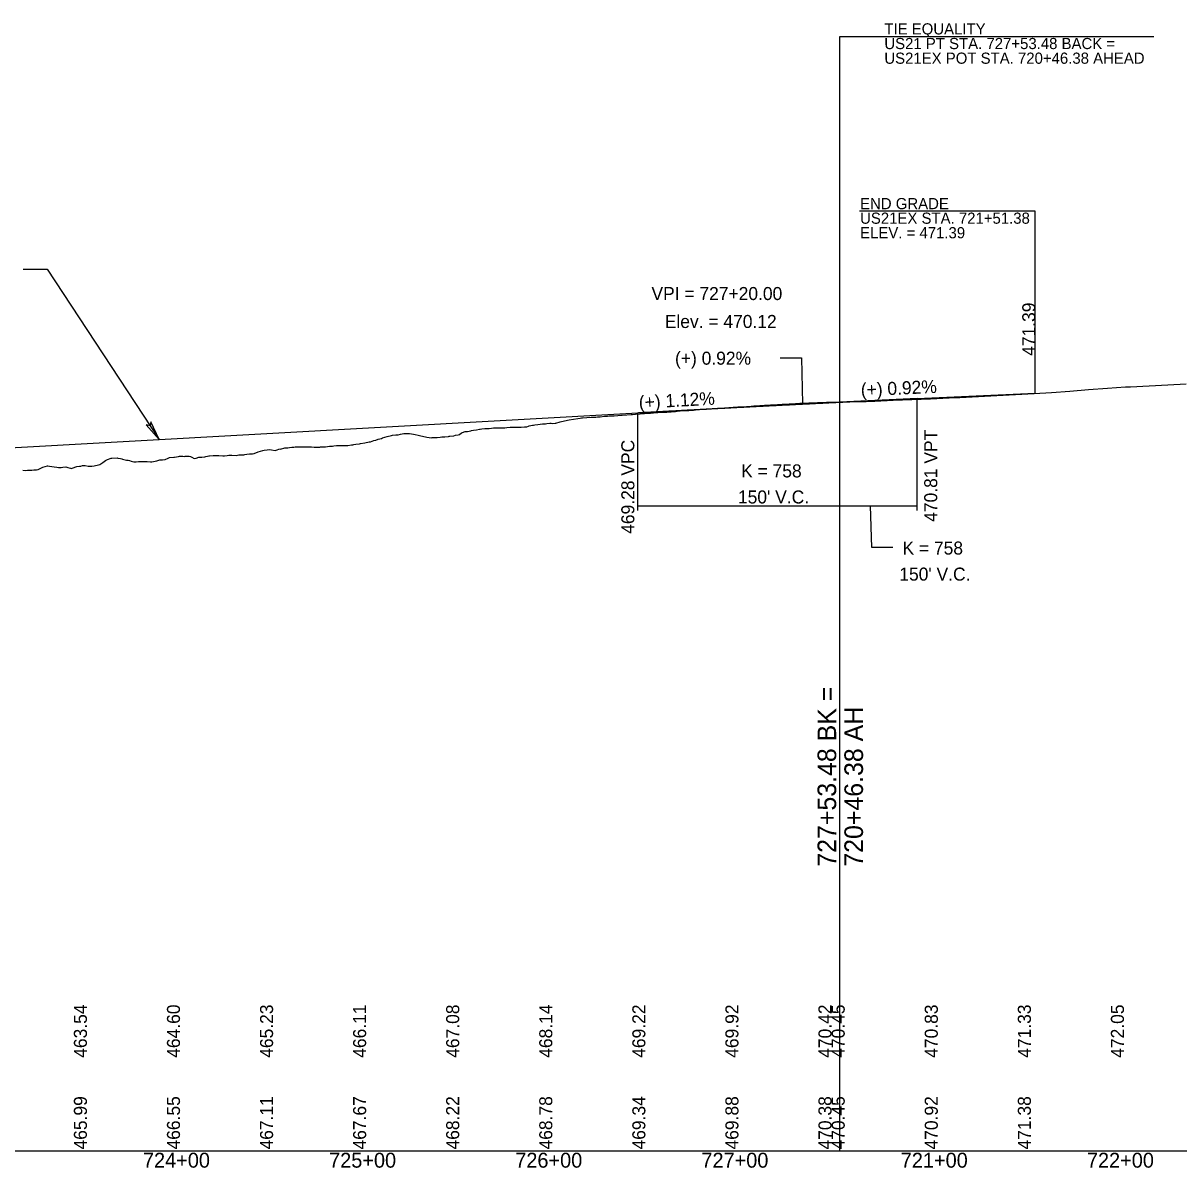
# Model space of a CAD drawing. Extents: x 2017200 to 2047700, y 854850 to 893350.
# Drawn here: x 2025315 to 2025936, y 889091 to 889706 of the extents above; entities that cross this region are included whole.
import ezdxf

# ---------------------------------------------------------------- set-up
doc = ezdxf.new("R2010")
doc.units = 0
for name, color, linetype in [('RD_DDB_GradeTX', 7, 'Continuous'), ('RD_DDB_Profile_EX', 7, 'Continuous'), ('RD_DDB_Profile_Lbl', 7, 'Continuous'), ('RD_DDB_Profile_PR', 7, 'Continuous'), ('RD_DDB_StaTX', 7, 'Continuous'), ('RD_DDB_StripGrade', 7, 'Continuous'), ('RD_DDB_VCLbl', 7, 'Continuous'), ('RD_GPK_Profile_Cell', 7, 'Continuous'), ('RD_PD_NON-PLOTTING', 7, 'Continuous')]:
    doc.layers.add(name, color=color, linetype=linetype)

msp = doc.modelspace()

# ---------------------------------------------------------------- linework, layer by layer
at = {"layer": 'RD_DDB_GradeTX'}
for p, q in [((2025645, 889496.42), (2025720, 889500.6)), ((2025753.48, 889502.14), (2025720, 889500.6)), ((2025795, 889504.04), (2025753.48, 889502.14))]:
    msp.add_line(p, q, dxfattribs=at)
for points in [[(2025721.48, 889525.92), (2025732.8, 889525.92), (2025733.46, 889501.22)], [(2025781.92, 889423.96), (2025770.6, 889423.96), (2025770, 889446.42)]]:
    msp.add_lwpolyline(points, dxfattribs=at)
at = {"layer": 'RD_DDB_Profile_EX'}
msp.add_lwpolyline([(2025314.65, 889465.57), (2025315.77, 889465.47), (2025317.04, 889465.48), (2025318.76, 889465.49), (2025319.42, 889465.57), (2025320.44, 889465.71), (2025321.87, 889465.81), (2025322.88, 889465.95), (2025324.19, 889466.64), (2025324.98, 889467.05), (2025325.33, 889467.21), (2025326.64, 889467.62), (2025327.78, 889467.86), (2025328.09, 889467.91), (2025328.96, 889467.75), (2025330.24, 889467.51), (2025331.35, 889467.31), (2025332.8, 889467.14), (2025333.73, 889467.01), (2025334.29, 889466.94), (2025335.17, 889466.92), (2025336.12, 889467.09), (2025337.64, 889467.34), (2025338.67, 889466.97), (2025340.12, 889466.58), (2025340.47, 889466.5), (2025341.06, 889466.72), (2025343.56, 889467.6), (2025345.09, 889467.68), (2025345.66, 889467.8), (2025346.65, 889468), (2025347.58, 889468.07), (2025348.04, 889468), (2025349.73, 889467.72), (2025350.08, 889467.72), (2025350.43, 889467.73), (2025351.59, 889467.78), (2025352.81, 889467.86), (2025355.2, 889468.39), (2025355.88, 889468.54), (2025357.6, 889469.73), (2025358.95, 889470.73), (2025360.12, 889471.34), (2025362.02, 889472.06), (2025362.35, 889472.07), (2025365.18, 889472.12), (2025365.62, 889472.07), (2025367.12, 889471.82), (2025367.72, 889471.71), (2025368.16, 889471.56), (2025369.51, 889471.18), (2025370.27, 889470.97), (2025371.22, 889470.85), (2025371.89, 889470.68), (2025372.82, 889470.44), (2025374.28, 889469.96), (2025375.37, 889469.97), (2025376.66, 889470.18), (2025377.33, 889470.3), (2025379.05, 889470.28), (2025380.5, 889470.24), (2025381.13, 889470.19), (2025381.43, 889470.16), (2025383.08, 889470.03), (2025383.44, 889470.07), (2025383.82, 889470.12), (2025385.66, 889470.39), (2025386.49, 889470.65), (2025388.25, 889471.13), (2025388.59, 889471.13), (2025389.53, 889471.12), (2025390.97, 889471.36), (2025392.58, 889471.93), (2025393.44, 889472.41), (2025395.74, 889472.54), (2025396.05, 889472.56), (2025398.12, 889472.95), (2025398.72, 889473.05), (2025400.51, 889473), (2025401.29, 889472.98), (2025401.7, 889473.1), (2025402.89, 889473.1), (2025403.92, 889473.09), (2025404.73, 889472.95), (2025405.28, 889472.61), (2025406.56, 889471.8), (2025407.77, 889472.09), (2025409.2, 889472.54), (2025410.05, 889472.55), (2025410.8, 889472.57), (2025412.43, 889472.78), (2025412.93, 889472.84), (2025413.83, 889473.16), (2025414.51, 889473.24), (2025414.82, 889473.28), (2025416.86, 889473.49), (2025417.2, 889473.52), (2025419.88, 889473.45), (2025421.97, 889473.35), (2025422.53, 889473.32), (2025422.91, 889473.34), (2025424.36, 889473.52), (2025425.22, 889473.63), (2025425.93, 889473.67), (2025426.84, 889473.6), (2025429.13, 889473.5), (2025430.62, 889473.87), (2025431.51, 889473.87), (2025431.98, 889473.88), (2025433.34, 889473.8), (2025433.9, 889473.9), (2025434.99, 889474.09), (2025436.28, 889474.28), (2025438.01, 889474.37), (2025438.79, 889474.52), (2025441.05, 889475.35), (2025443.44, 889476.07), (2025444.27, 889476.29), (2025445.82, 889476.49), (2025447.09, 889476.66), (2025448.21, 889476.47), (2025450.07, 889476.16), (2025450.59, 889476.32), (2025452.57, 889476.94), (2025453.08, 889476.92), (2025455.36, 889477.53), (2025456.09, 889477.55), (2025456.95, 889477.62), (2025457.75, 889477.72), (2025459.1, 889477.9), (2025460.13, 889477.98), (2025460.95, 889478.05), (2025462.11, 889478.1), (2025462.52, 889478.1), (2025463.76, 889478.11), (2025465.12, 889478.15), (2025466.58, 889478.12), (2025467.29, 889478.1), (2025468.12, 889478.06), (2025469.67, 889478.01), (2025471.13, 889477.98), (2025472.06, 889477.99), (2025473.05, 889478), (2025474.13, 889478), (2025474.44, 889478.01), (2025475.11, 889478.03), (2025476.83, 889478.14), (2025477.14, 889478.16), (2025479.38, 889478.42), (2025480.14, 889478.46), (2025480.84, 889478.5), (2025481.6, 889478.58), (2025483.14, 889478.74), (2025483.98, 889478.77), (2025485.64, 889478.83), (2025486.62, 889478.83), (2025488.75, 889478.88), (2025489.15, 889478.89), (2025491.14, 889479.13), (2025491.85, 889479.21), (2025492.44, 889479.31), (2025493.52, 889479.46), (2025495.37, 889479.72), (2025495.91, 889479.8), (2025498.31, 889480.18), (2025500.68, 889480.73), (2025501.26, 889480.87), (2025503.06, 889481.41), (2025504.22, 889481.76), (2025505.45, 889482.13), (2025507.2, 889482.65), (2025507.83, 889482.85), (2025510.22, 889483.61), (2025512.6, 889484.2), (2025513.18, 889484.35), (2025514.99, 889484.5), (2025516.16, 889484.59), (2025517.37, 889484.85), (2025519.22, 889485.23), (2025519.76, 889485.23), (2025522.26, 889485.21), (2025524.53, 889484.82), (2025525.31, 889484.67), (2025526.91, 889484.34), (2025528.38, 889484.04), (2025529.3, 889483.84), (2025531.68, 889483.37), (2025534.17, 889483.02), (2025534.55, 889483.03), (2025536.45, 889483.11), (2025537.17, 889483.14), (2025538.84, 889483.32), (2025539.6, 889483.4), (2025540.17, 889483.44), (2025540.79, 889483.51), (2025541.22, 889483.55), (2025543.17, 889483.72), (2025543.61, 889483.77), (2025543.92, 889483.81), (2025546.18, 889484.09), (2025547.08, 889484.3), (2025548.38, 889484.61), (2025549.18, 889484.8), (2025550.25, 889485.56), (2025550.76, 889485.75), (2025552.19, 889486.26), (2025553.43, 889486.37), (2025555.19, 889486.72), (2025555.53, 889486.8), (2025556.63, 889487.04), (2025558.2, 889487.25), (2025559.85, 889487.51), (2025560.3, 889487.62), (2025561.21, 889487.83), (2025562.69, 889487.86), (2025563.08, 889487.86), (2025564.21, 889487.99), (2025565.07, 889488.02), (2025566.33, 889488.08), (2025567.46, 889488.23), (2025567.98, 889488.29), (2025569.84, 889488.34), (2025570.23, 889488.35), (2025572.22, 889488.34), (2025572.89, 889488.34), (2025573.54, 889488.37), (2025574.61, 889488.45), (2025576.31, 889488.57), (2025576.99, 889488.57), (2025579.52, 889488.57), (2025581.76, 889488.64), (2025582.29, 889488.65), (2025584.15, 889488.86), (2025584.56, 889488.9), (2025585.3, 889488.89), (2025586.22, 889489.25), (2025586.53, 889489.32), (2025588.32, 889489.68), (2025588.92, 889489.75), (2025589.6, 889489.83), (2025591.3, 889490.11), (2025593.8, 889490.52), (2025595.43, 889490.42), (2025596.07, 889490.55), (2025597.66, 889490.87), (2025598.46, 889490.73), (2025599.18, 889490.6), (2025600.48, 889490.77), (2025600.84, 889490.86), (2025603.23, 889491.45), (2025605.61, 889492.03), (2025608.1, 889492.63), (2025610.38, 889492.99), (2025612.77, 889493.36), (2025614.02, 889493.56), (2025614.69, 889493.62), (2025615.15, 889493.65), (2025617.54, 889493.8), (2025619.92, 889493.95), (2025622.31, 889494.1), (2025623.29, 889494.16), (2025624.69, 889494.28), (2025627.08, 889494.49), (2025628.72, 889494.63), (2025629.46, 889494.68), (2025631.85, 889494.81), (2025632.24, 889494.83), (2025634.23, 889495.01), (2025635.61, 889495.14), (2025636.62, 889495.19), (2025639, 889495.33), (2025641.39, 889495.47), (2025642.04, 889495.51), (2025643.77, 889495.67), (2025646.16, 889495.88), (2025646.53, 889495.92), (2025648.54, 889496.03), (2025650.93, 889496.17), (2025651.84, 889496.22), (2025653.31, 889496.34), (2025655.7, 889496.51), (2025658.08, 889496.65), (2025659.96, 889496.75), (2025660.47, 889496.79), (2025662.85, 889496.97), (2025665.24, 889497.14), (2025666.04, 889497.2), (2025667.65, 889497.35), (2025670.01, 889497.52), (2025672.39, 889497.69), (2025674.78, 889497.85), (2025677.16, 889498.07), (2025677.68, 889498.12), (2025679.55, 889498.24), (2025681.93, 889498.39), (2025684.32, 889498.55), (2025685.44, 889498.62), (2025686.7, 889498.73), (2025687.69, 889498.81), (2025689.09, 889498.9), (2025691.47, 889499.04), (2025693.86, 889499.19), (2025696.24, 889499.33), (2025697.7, 889499.45), (2025698.63, 889499.51), (2025701.01, 889499.66), (2025703.4, 889499.81), (2025705.78, 889499.96), (2025706.08, 889499.98), (2025707.21, 889500.05), (2025708.17, 889500.1), (2025710.55, 889500.25), (2025712.94, 889500.39), (2025715.32, 889500.54), (2025716.22, 889500.59), (2025716.98, 889500.64), (2025717.71, 889500.68), (2025720.09, 889500.82), (2025722.48, 889500.96), (2025724.86, 889501.09), (2025726.32, 889501.18), (2025726.81, 889501.2), (2025727.25, 889501.23), (2025729.63, 889501.36), (2025732.02, 889501.49), (2025734.4, 889501.62), (2025736.79, 889501.75), (2025737.63, 889501.77), (2025739.17, 889501.81), (2025741.56, 889501.88), (2025743.94, 889501.94), (2025746.32, 889502), (2025747.63, 889502.03), (2025748.71, 889502.06), (2025751.09, 889502.12), (2025753.48, 889502.17), (2025757.63, 889502.27), (2025767.63, 889502.51), (2025772.19, 889502.7), (2025782.2, 889503.11), (2025792.22, 889503.53), (2025802.23, 889503.95), (2025812.16, 889504.36), (2025817.9, 889504.65), (2025827.9, 889505.15), (2025837.9, 889505.66), (2025847.9, 889506.17), (2025857.9, 889506.68), (2025867.22, 889507.36), (2025877.04, 889508.07), (2025887.04, 889508.8), (2025897.22, 889509.53), (2025907.01, 889510.24), (2025909.61, 889510.36), (2025919.62, 889510.86), (2025929.62, 889511.35), (2025939.56, 889511.85)], dxfattribs=at)
at = {"layer": 'RD_DDB_Profile_Lbl'}
for points in [[(2025753.48, 889502.08), (2025753.48, 889698.54), (2025922.23, 889698.54)], [(2025858.48, 889506.95), (2025858.48, 889604.61), (2025764.12, 889604.61)], [(2025314.77, 889573.48), (2025327.63, 889573.48), (2025387.8, 889482.08)]]:
    msp.add_lwpolyline(points, dxfattribs=at)
msp.add_lwpolyline([(2025387.8, 889482.08), (2025383.34, 889491.58), (2025382.97, 889489.42), (2025380.84, 889489.93)], close=True, dxfattribs=at)
at = {"layer": 'RD_DDB_Profile_PR'}
for p, q in [((2025795, 889504.04), (2025858.48, 889506.95)), ((2024325, 889422.83), (2025645, 889496.42))]:
    msp.add_line(p, q, dxfattribs=at)
for points in [[(2025645, 889496.42), (2025647.17, 889496.54), (2025649.34, 889496.66), (2025651.51, 889496.78), (2025653.68, 889496.9), (2025655.85, 889497.02), (2025658.02, 889497.14), (2025660.19, 889497.26), (2025662.36, 889497.38), (2025664.53, 889497.49), (2025666.7, 889497.61), (2025668.87, 889497.73), (2025671.04, 889497.85), (2025673.2, 889497.96), (2025675.37, 889498.08), (2025677.54, 889498.2), (2025679.71, 889498.31), (2025681.88, 889498.43), (2025684.05, 889498.55), (2025686.22, 889498.66), (2025688.39, 889498.78), (2025690.56, 889498.89), (2025692.73, 889499), (2025694.9, 889499.12), (2025697.07, 889499.23), (2025699.24, 889499.35), (2025701.41, 889499.46), (2025703.58, 889499.57), (2025705.75, 889499.68), (2025707.92, 889499.8), (2025710.09, 889499.91), (2025712.26, 889500.02), (2025714.43, 889500.13), (2025716.6, 889500.24), (2025718.77, 889500.35), (2025720.94, 889500.46), (2025723.11, 889500.57), (2025725.27, 889500.68), (2025727.44, 889500.79), (2025729.61, 889500.9), (2025731.78, 889501.01), (2025733.95, 889501.12), (2025736.12, 889501.22), (2025738.29, 889501.33), (2025740.46, 889501.44), (2025742.63, 889501.55), (2025744.8, 889501.65), (2025746.97, 889501.76), (2025749.14, 889501.87), (2025751.31, 889501.97), (2025753.48, 889502.08)], [(2025753.48, 889502.08), (2025754.31, 889502.12), (2025755.14, 889502.16), (2025755.97, 889502.2), (2025756.8, 889502.24), (2025757.63, 889502.28), (2025758.46, 889502.32), (2025759.29, 889502.36), (2025760.12, 889502.4), (2025760.95, 889502.44), (2025761.78, 889502.48), (2025762.61, 889502.52), (2025763.44, 889502.56), (2025764.27, 889502.6), (2025765.11, 889502.64), (2025765.94, 889502.68), (2025766.77, 889502.72), (2025767.6, 889502.76), (2025768.43, 889502.8), (2025769.26, 889502.84), (2025770.09, 889502.88), (2025770.92, 889502.92), (2025771.75, 889502.96), (2025772.58, 889502.99), (2025773.41, 889503.03), (2025774.24, 889503.07), (2025775.07, 889503.11), (2025775.9, 889503.15), (2025776.73, 889503.19), (2025777.56, 889503.23), (2025778.39, 889503.27), (2025779.22, 889503.31), (2025780.05, 889503.35), (2025780.88, 889503.39), (2025781.71, 889503.42), (2025782.54, 889503.46), (2025783.37, 889503.5), (2025784.2, 889503.54), (2025785.04, 889503.58), (2025785.87, 889503.62), (2025786.7, 889503.66), (2025787.53, 889503.69), (2025788.36, 889503.73), (2025789.19, 889503.77), (2025790.02, 889503.81), (2025790.85, 889503.85), (2025791.68, 889503.89), (2025792.51, 889503.92), (2025793.34, 889503.96), (2025794.17, 889504), (2025795, 889504.04)]]:
    msp.add_spline(points, degree=3, dxfattribs=at)
at = {"layer": 'RD_DDB_VCLbl'}
for p, q in [((2025795, 889443.92), (2025795, 889504.04)), ((2025645, 889443.92), (2025645, 889496.42)), ((2025645, 889446.42), (2025753.48, 889446.42)), ((2025753.48, 889446.42), (2025795, 889446.42))]:
    msp.add_line(p, q, dxfattribs=at)
at = {"layer": 'RD_GPK_Profile_Cell'}
msp.add_line((2020500, 889100), (2027000, 889100), dxfattribs=at)
at = {"layer": 'RD_PD_NON-PLOTTING'}
msp.add_line((2025753.48, 889100), (2025753.48, 889512.23), dxfattribs=at)

# ---------------------------------------------------------------- texts
at = {"layer": 'RD_DDB_GradeTX'}
msp.add_text('(+) 0.92%', height=7, dxfattribs=at).set_placement((2025664.94, 889522.2))
for s, rotation, p in [('(+) 0.92%', 2.62549, (2025764.9, 889505.2)), ('(+) 1.12%', 3.19108, (2025645.68, 889498.46))]:
    msp.add_text(s, height=7, rotation=rotation, dxfattribs=at).set_placement(p)
at = {"layer": 'RD_DDB_Profile_Lbl'}
for s, height, p in [('TIE EQUALITY', 6, (2025777.38, 889699.55)), ('TIE EQUALITY', 6, (2025777.38, 889699.55)), ('US21 PT STA. 727+53.48 BACK = ', 6, (2025777.38, 889691.68)), ('US21 PT STA. 727+53.48 BACK =', 6, (2025777.38, 889691.68)), ('US21EX POT STA. 720+46.38 AHEAD', 6, (2025777.38, 889683.81)), ('US21EX POT STA. 720+46.38 AHEAD', 6, (2025777.38, 889683.81)), ('VPI = 727+20.00', 7, (2025652.29, 889556.92)), ('Elev. = 470.12', 7, (2025659.44, 889541.92))]:
    msp.add_text(s, height=height, dxfattribs=at).set_placement(p)
for s, height, rotation, p in [('END GRADE', 6, 360, (2025764.35, 889605.71)), ('US21EX STA. 721+51.38', 6, 360, (2025764.35, 889597.89)), ('ELEV. = 471.39', 6, 360, (2025764.35, 889590.08)), ('471.39', 7, 90, (2025858.48, 889526.95))]:
    msp.add_text(s, height=height, rotation=rotation, dxfattribs=at).set_placement(p)
at = {"layer": 'RD_DDB_StaTX'}
for s, p in [('724+00', (2025379.1, 889091)), ('725+00', (2025479.1, 889091)), ('726+00', (2025579.1, 889091)), ('727+00', (2025679.1, 889091)), ('721+00', (2025786.2, 889091)), ('722+00', (2025886.2, 889091))]:
    msp.add_text(s, height=8, dxfattribs=at).set_placement(p)
at = {"layer": 'RD_DDB_StripGrade'}
for s, p in [('470.81 VPT', (2025805.8, 889437.83)), ('469.28 VPC', (2025643.08, 889431.39)), ('463.54', (2025349, 889150)), ('464.60', (2025399, 889150)), ('465.23', (2025449, 889150)), ('466.11', (2025499, 889150)), ('467.08', (2025549, 889150)), ('468.14', (2025599, 889150)), ('469.22', (2025649, 889150)), ('469.92', (2025699, 889150)), ('470.42', (2025749, 889150)), ('470.45', (2025756.1, 889150)), ('470.83', (2025806.1, 889150)), ('471.33', (2025856.1, 889150)), ('472.05', (2025906.1, 889150)), ('465.99', (2025349, 889100.75)), ('466.55', (2025399, 889100.75)), ('467.11', (2025449, 889100.75)), ('467.67', (2025499, 889100.75)), ('468.22', (2025549, 889100.75)), ('468.78', (2025599, 889100.75)), ('469.34', (2025649, 889100.75)), ('469.88', (2025699, 889100.75)), ('470.38', (2025749, 889100.75)), ('470.45', (2025756.1, 889100.75)), ('470.92', (2025806.1, 889100.75)), ('471.38', (2025856.1, 889100.75))]:
    msp.add_text(s, height=7, rotation=90, dxfattribs=at).set_placement(p)
at = {"layer": 'RD_DDB_VCLbl'}
for s, p in [('K = 758', (2025700.44, 889461.67)), ("150' V.C.", (2025698.75, 889447.67)), ('K = 758', (2025787.12, 889420.25)), ("150' V.C.", (2025785.43, 889406.25))]:
    msp.add_text(s, height=7, dxfattribs=at).set_placement(p)
at = {"layer": 'RD_PD_NON-PLOTTING'}
for s, p in [('727+53.48 BK = ', (2025751.51, 889252.63)), ('720+46.38 AH', (2025765.92, 889252.63))]:
    msp.add_text(s, height=10, rotation=90, dxfattribs=at).set_placement(p)

doc.saveas('drawing.dxf')
